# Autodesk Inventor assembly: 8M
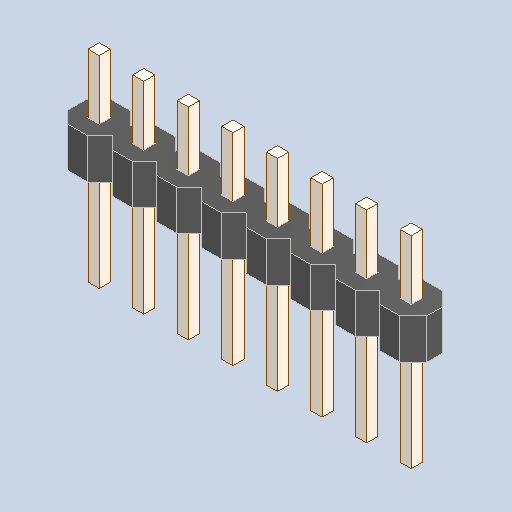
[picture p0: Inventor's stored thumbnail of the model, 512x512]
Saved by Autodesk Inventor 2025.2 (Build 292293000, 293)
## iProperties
Created: 2025-04
Part Number: 8M
Description: PART--DESC
Document SubType Name: Assembly
Designer: BennF
Author: BennF
Revision Number: NONE
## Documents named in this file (3)
- C:\Users\BennF\Nextcloud\Benutzer\CNC JarBeRi\existing parts\Electronics\RepRap A4988 Shied (USE WITHOUT ARDUINO)\reprap-a4988-1.snapshot.1\RepRap\RepRap\8M_2.iam
- C:\Users\BennF\Nextcloud\Benutzer\CNC JarBeRi\existing parts\Electronics\RepRap A4988 Shied (USE WITHOUT ARDUINO)\reprap-a4988-1.snapshot.1\RepRap\RepRap\8M Geometry.ipt
- C:\Users\BennF\Nextcloud\Benutzer\CNC JarBeRi\existing parts\Electronics\RepRap A4988 Shied (USE WITHOUT ARDUINO)\reprap-a4988-1.snapshot.1\RepRap\RepRap\pin4.ipt
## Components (2 placed, 2 different names)
1. 8M Geometry
2. pin4
